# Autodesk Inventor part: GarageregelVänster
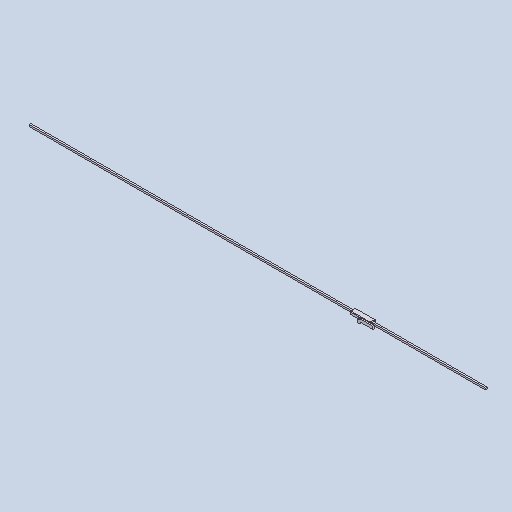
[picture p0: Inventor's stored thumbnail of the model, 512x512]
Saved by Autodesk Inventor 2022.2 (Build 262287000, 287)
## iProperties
Created: 2019-06
Part Number: GarageregelVänster
Material: Aluminum 6061, Welded
Document SubType Name: Modeling
Designer: cl
Density: 2.7 g/cm^3
Appearance: Weld - Aluminum
Author: cl
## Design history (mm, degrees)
sketch "Sketch1"
  geometry: L1 (5, 0)-(175, 0); L2 (180, -5)-(180, -45); L3 (175, -50)-(5, -50); L4 (0, -45)-(0, -5); A1 r 5 centre (175, -5) between (180, -5) and (175, 0); A2 r 5 centre (175, -45) between (175, -50) and (180, -45); A3 r 5 centre (5, -45) between (0, -45) and (5, -50); A4 r 5 centre (5, -5) between (5, 0) and (0, -5); 4 further points
  constraints: 8 end point, 8 point on circle, 8 point on line, 8 tangent, 4 centre point, 3 equal radius, 2 parallel, 1 horizontal, 1 perpendicular
  dimensions: "d0" = 180 distance of point (180, -50) point (0, -50); "d1" = 50 distance of point (180, 0) point (180, -50); "d2" = 5 radius of A1
extrude "Extrusion1" new body sketch "Sketch1" distance "d3" = 22; taper "d4" = 0 deg
fillet "Fillet1" dims "d5" = 5
workplane "Work Plane1"
sketch "Sketch2"
  geometry: L1 (175, 0)-(5, 0) reference; L2 (100, 0)-(67.861, 38.302); L3 (180, -45)-(180, -5) reference; L4 (175, 0)-(5, 0) reference; L5 (100, 0)-(73.892, 0); L6 (73.892, 0)-(52.54, 25.446); L7 (67.861, 38.302)-(52.54, 25.446); 3 further points
  constraints: 8 end point, 2 point on line, 1 parallel, 1 perpendicular
  dimensions: "d7" = 80 distance from line of L3 L2.start; "d9" = 50 distance of L2.start L2.end; "d10" = 20 distance between parallel lines of L2 L6; "d27" = 130 deg angle of L1 L2
extrude "Extrusion2" join sketch "Sketch2" stored distance "d11" = 10; taper "d12" = 0 deg
sketch "Sketch3"
  geometry: L1 (-78.648, 38.302)-(-53.648, 38.302); L2 (-38.648, 38.302)-(-38.648, 25.446); L3 (-38.648, 25.446)-(-53.648, 25.446); L4 (-78.648, 25.446)-(-78.648, 38.302); L5 (-100, 0)-(-67.861, 38.302) reference; L6 (-53.648, 38.302)-(-53.648, 25.446); L7 (-53.648, 38.302)-(-38.648, 38.302); L8 (-53.648, 25.446)-(-78.648, 25.446); 2 further points
  constraints: 14 end point, 5 parallel, 4 perpendicular, 4 point on line, 2 horizontal
  dimensions: "d13" = 40 distance of L1.start L2.start; "d15" = 25 distance between parallel lines of L4 L6
revolve "Revolution1" sketch "Sketch3" stored, may be unused: angle "d14" = 90 deg
fillet "Fillet2" dims "d16" = 2
fillet "Fillet3" dims "d17" = 2
sketch "Sketch4"
  geometry: L1 (-12.856, 25)-(-12.856, 0) reference; L2 (-12.856, 25)-(0, 25); L3 (0, 25)-(0, 0); L4 (0, 0)-(-12.856, 0); L5 (-12.856, 0)-(-12.856, 25); L6 (0, 0)-(0, 25) reference; L7 (-12.856, 0)-(0, 0) reference; 2 further points
  constraints: 8 end point, 2 collinear, 2 parallel, 1 horizontal, 1 perpendicular
extrude "Extrusion3" join sketch "Sketch4" distance "d18" = 100; taper "d19" = 0 deg
sketch "Sketch5"
  geometry: L1 (0, 0)-(40, 0) reference; L2 (27.5, 0)-(12.5, 0); L3 (12.5, 0)-(12.5, 15); L4 (12.5, 15)-(27.5, 15); L5 (27.5, 15)-(27.5, 0); L6 (45, 0)-(45, 17) reference
  constraints: 8 end point, 2 parallel, 1 horizontal, 1 perpendicular, 1 point on line
  dimensions: "d20" = 15 distance of L3.end L4.end; "d21" = 15 distance of L2.end L3.end; "d22" = 17.5 distance between parallel lines of L6 L5
extrude "Extrusion4" join sketch "Sketch5" distance "d23" = 2845 (computed from Daghöjd_1); taper "d25" = 0 deg; dims "d24" = 1180, "d26" = 0
body "Solid1"
other parameters: "d6" = 11, "BladBredd" = 987.5, "Fönsterhöjd" = 862
